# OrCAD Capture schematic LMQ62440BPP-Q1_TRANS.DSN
size D; title: LMQ62440BPP-Q1 Automotive 3-V to 36-V, 4-A, Low EMI; rev: 1.0; note: Datasheet:SNVSBQ0A       EVM:SNVU697; note: Synchronous Step-Down Converter
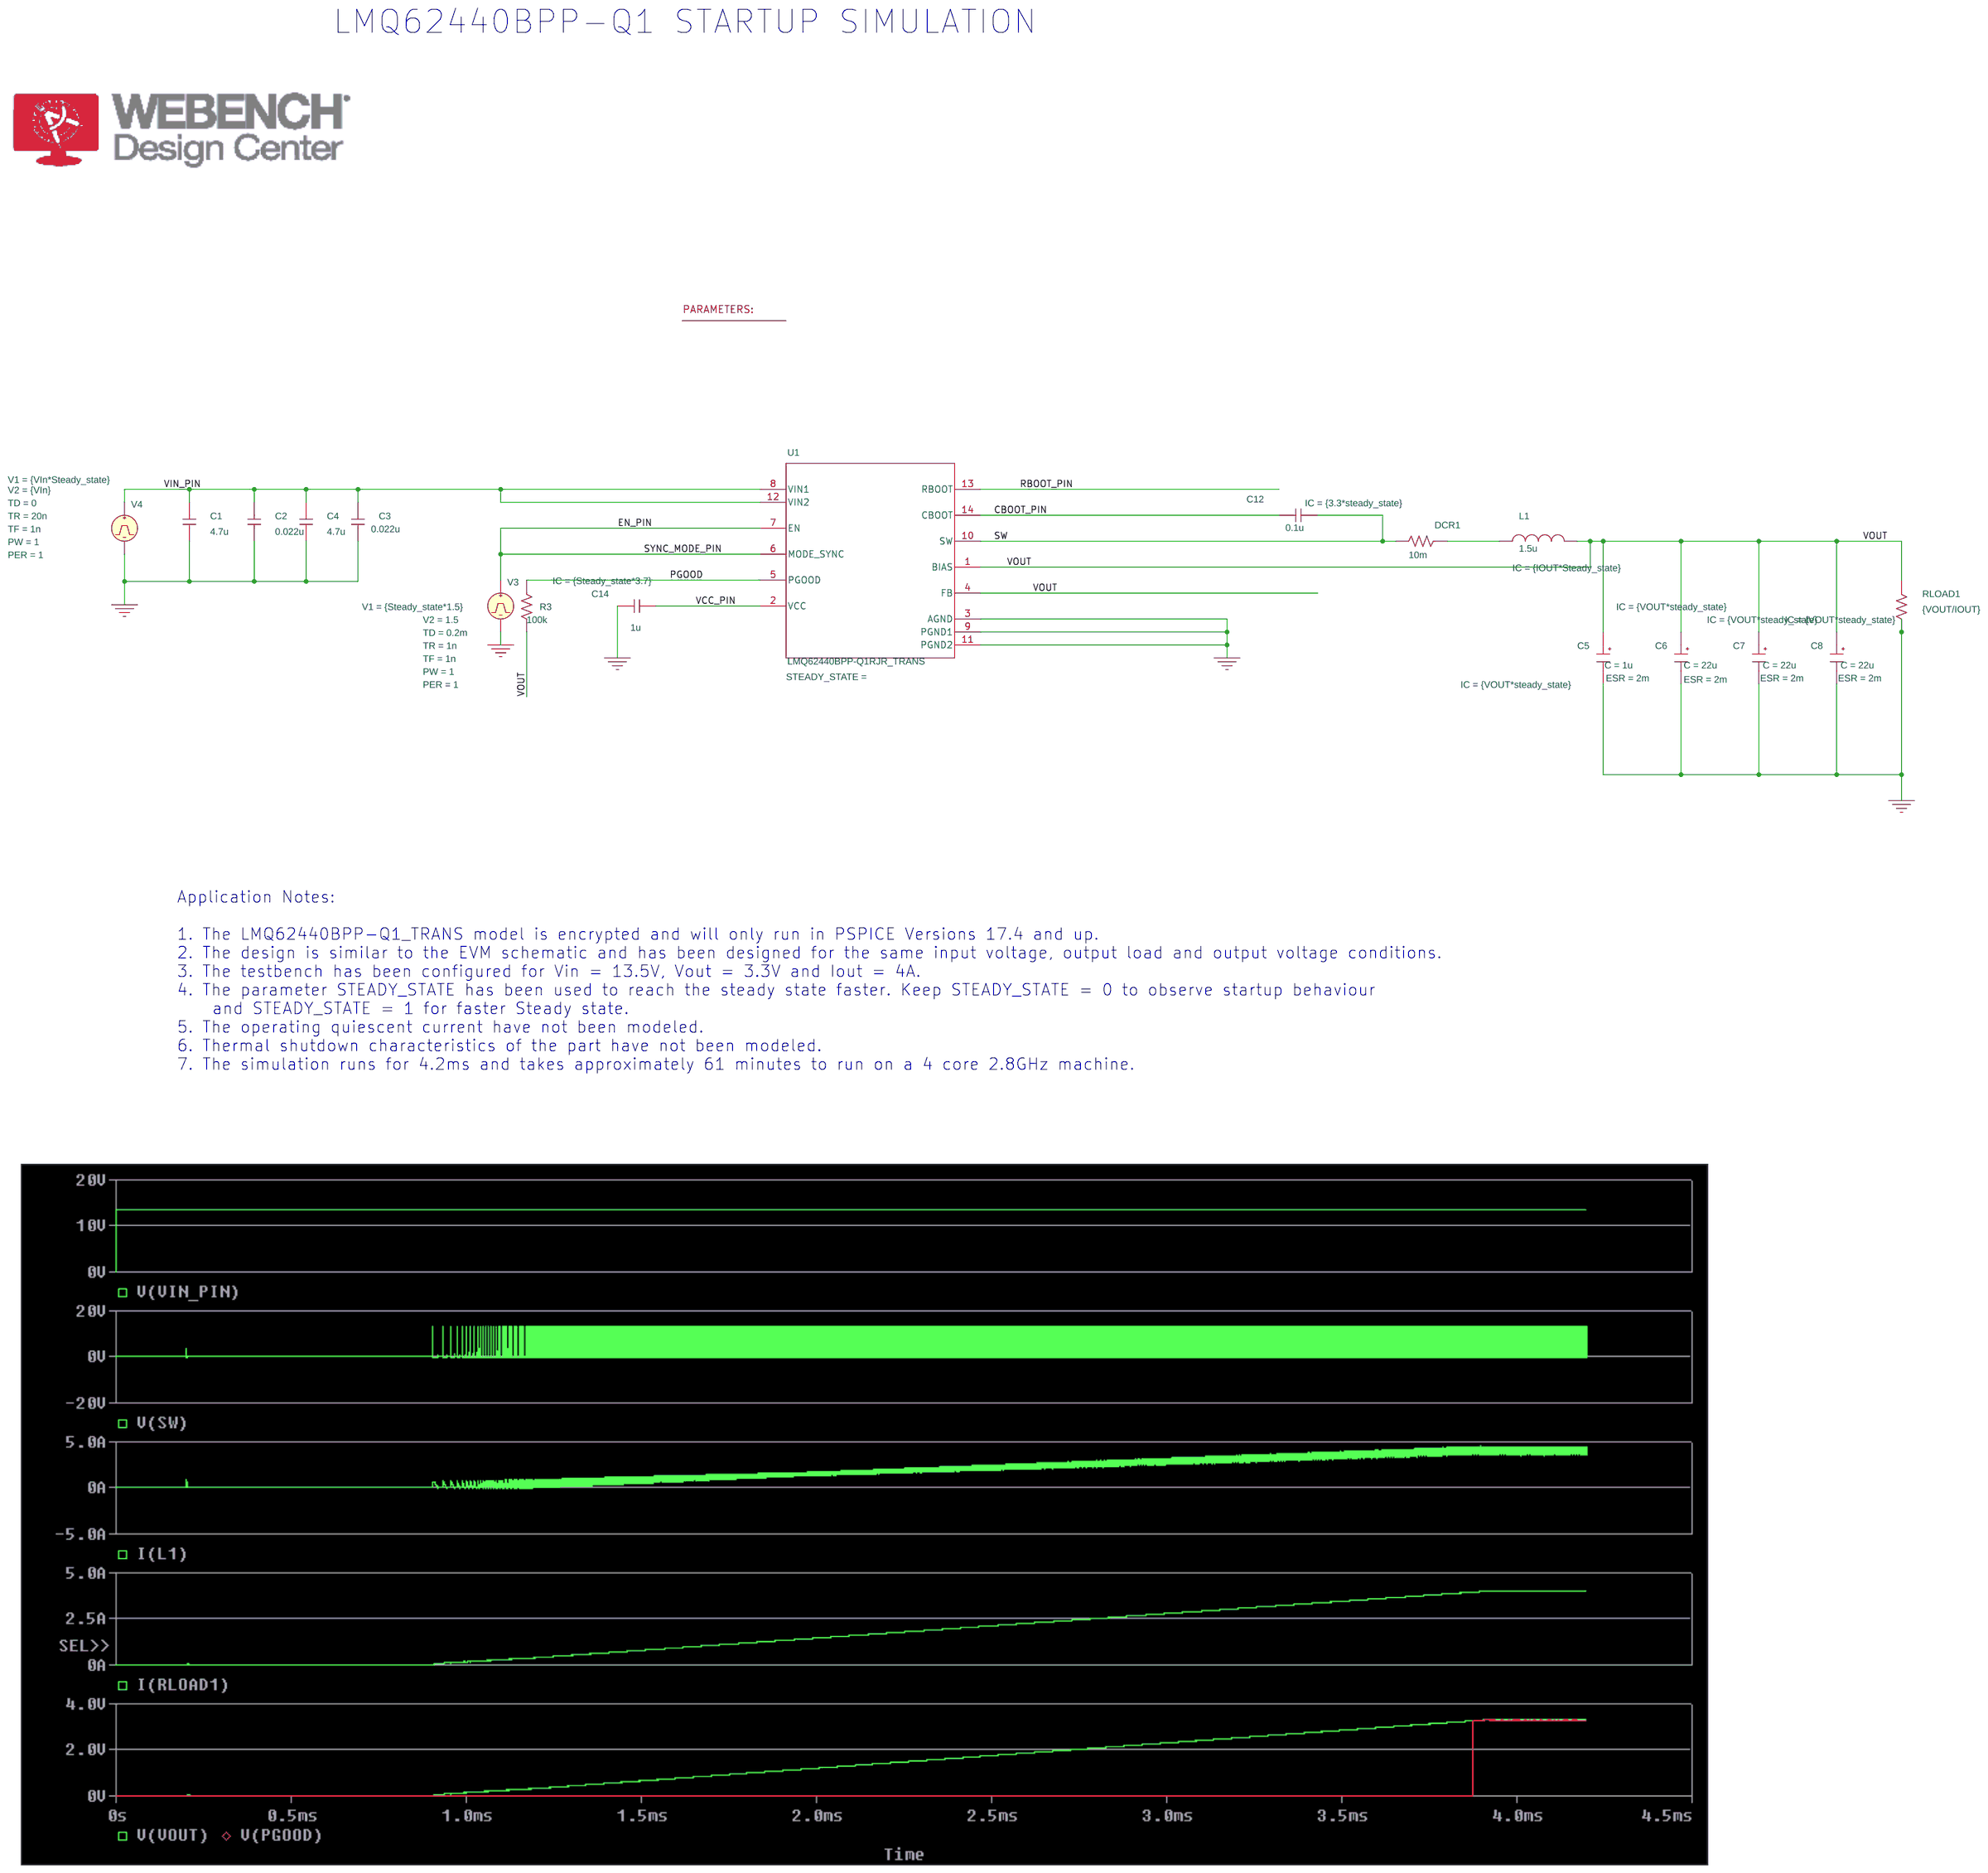
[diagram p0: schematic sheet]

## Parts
1  PARAM
C1  4.7u  [RAD/CK05]
C2  0.022u  [RAD/CK05]
C3  0.022u  [RAD/CK05]
C4  4.7u  [RAD/CK05]
C5  CESR
C6  CESR
C7  CESR
C8  CESR
C12  0.1u  [RAD/CK05]
C14  1u  [RAD/CK05]
DCR1  10m  [AX/RC05]
L1  1.5u  [DISC/.350x.175/LS.200x.100/.034]
R3  100k  [AX/RC05]
RLOAD1  {VOUT/IOUT}  [AX/RC05]
U1  LMQ62440BPP-Q1RJR_TRANS  [RJR0014A-MFG]
V3  VPULSE
V4  VPULSE

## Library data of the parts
1 = PARAM: Iout: 4; Steady_state: 0; VIn: 13.5; Vout: 3.3
C1-C4 = C
C5 = CESR_0: C: 1u; ESR: 2m; IC: {VOUT*steady_state}; PSpiceTemplate: X^@REFDES %IN %OUT @MODEL PARAMS:  ?C|C=@C||C=100u|  ?ESR|ESR=@ESR||ESR=0.01| ?X|X=@X||X=2|  ?IC|IC=@IC||IC=2|; X: 1
C6-C8 = CESR_0: C: 22u; ESR: 2m; IC: {VOUT*steady_state}; PSpiceTemplate: X^@REFDES %IN %OUT @MODEL PARAMS:  ?C|C=@C||C=100u|  ?ESR|ESR=@ESR||ESR=0.01| ?X|X=@X||X=2|  ?IC|IC=@IC||IC=2|; X: 1
C12 = C: IC: {3.3*steady_state}
C14 = C: IC: {Steady_state*3.7}
DCR1 R3 RLOAD1 = R
L1 = L: IC: {IOUT*Steady_state}
U1 = LMQ62440BPP-Q1RJR_TRANS
V3 = VPULSE: PER: 1; PW: 1; TD: 0.2m; TF: 1n; TR: 1n; V1: {Steady_state*1.5}; V2: 1.5
V4 = VPULSE: PER: 1; PW: 1; TD: 0; TF: 1n; TR: 20n; V1: {VIn*Steady_state}; V2: {VIn}

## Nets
VCC_PIN: C14.1 U1.2(VCC)
VIN_PIN: C1.1 C2.1 C3.1 C4.1 U1.8(VIN1) U1.12(VIN2) V4.1(+)
0: C1.2 C2.2 C3.2 C4.2 C5.2(OUT) C6.2(OUT) C7.2(OUT) C8.2(OUT) C14.2 RLOAD1.2 U1.3(AGND) U1.9(PGND1) U1.11(PGND2) V3.2(-) V4.2(-)
CBOOT_PIN: C12.1 U1.14(CBOOT)
EN_PIN: U1.6(MODE_SYNC) U1.7(EN) V3.1(+)
PGOOD: R3.1 U1.5(PGOOD)
RBOOT_PIN: U1.13(RBOOT)
SW: C12.2 DCR1.2 U1.10(SW)
VOUT: C5.1(IN) C6.1(IN) C7.1(IN) C8.1(IN) L1.2 R3.2 RLOAD1.1 U1.1(BIAS) U1.4(FB)
N16793252: DCR1.1 L1.1

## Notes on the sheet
- LMQ62440BPP-Q1 STARTUP SIMULATION
- Application Notes:
  1. The LMQ62440BPP-Q1_TRANS model is encrypted and will only run in PSPICE Versions 17.4 and up.
  2. The design is similar to the EVM schematic and has been designed for the same input voltage, output load and output voltage conditions.
  3. The testbench has been configured for Vin = 13.5V, Vout = 3.3V and Iout = 4A.
  4. The parameter STEADY_STATE has been used to reach the steady state faster. Keep STEADY_STATE = 0 to observe startup behaviour
      and STEADY_STATE = 1 for faster Steady state.
  5. The operating quiescent current have not been modeled.
  6. Thermal shutdown characteristics of the part have not been modeled.
  7. The simulation runs for 4.2ms and takes approximately 61 minutes to run on a 4 core 2.8GHz machine.
